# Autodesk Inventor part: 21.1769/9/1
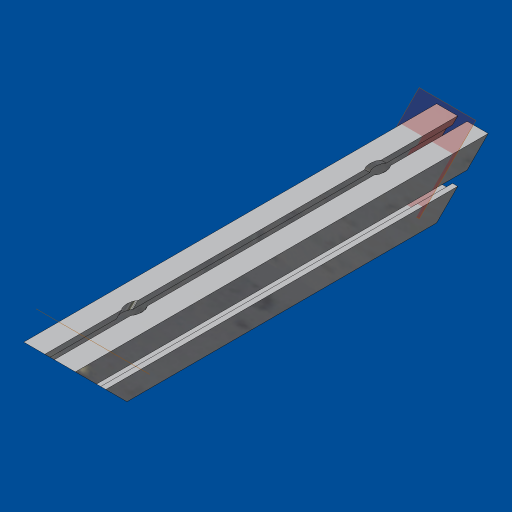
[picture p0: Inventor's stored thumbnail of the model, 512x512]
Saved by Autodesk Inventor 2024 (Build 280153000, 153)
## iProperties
Created: 2024-02
Part Number: 21.1769/9/1
Material: Aluminum-6061
Description: L = 14.17", MITER CUT & MILL TO 21.1761/9/1
Document SubType Name: Modeling
Designer: amoles
Stock Number: 20.1033 PROFILE 45X45 F
Density: 2.71 g/cm^3
Appearance: Aluminum - Dark
Vendor: F
FINISH: CLEAR ANODIZED
Author: amoles
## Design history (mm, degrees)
sketch "Sketch1"
  geometry: L1 (-4.1, -22.5)-(-4.1, -18) reference; L2 (-4.6, -18)-(-6.8, -18) reference; L3 (-6.8, -18)-(-6.8, -9.5) reference; L4 (-6.8, -9.5)-(-4.5, -7.2) reference; L5 (-4.5, -7.2)-(4.5, -7.2) reference; L6 (4.5, -7.2)-(6.8, -9.5) reference; L7 (6.8, -9.5)-(6.8, -18) reference; L8 (4.1, -18)-(4.1, -22.5) reference; L9 (22.5, -4.1)-(18, -4.1) reference; L10 (18, -4.6)-(18, -6.8) reference; L11 (18, -6.8)-(9.5, -6.8) reference; L12 (9.5, -6.8)-(7.2, -4.5) reference; L13 (7.2, -4.5)-(7.2, 4.5) reference; L14 (7.2, 4.5)-(9.5, 6.8) reference; L15 (9.5, 6.8)-(18, 6.8) reference; L16 (18, 4.1)-(22.5, 4.1) reference; L17 (22.5, 22.5)-(22.5, 4.4) reference; L18 (4.1, 22.5)-(4.1, 18) reference; L19 (4.6, 18)-(6.8, 18) reference; L20 (6.8, 18)-(6.8, 9.5) reference; L21 (6.8, 9.5)-(4.5, 7.2) reference; L22 (4.5, 7.2)-(-4.5, 7.2) reference; L23 (-4.5, 7.2)-(-6.8, 9.5) reference; L24 (-6.8, 9.5)-(-6.8, 18) reference; L25 (-4.1, 18)-(-4.1, 22.5) reference; L26 (-22.5, 22.5)-(-4.4, 22.5) reference; L27 (-22.5, 4.1)-(-18, 4.1) reference; L28 (-18, 6.8)-(-9.5, 6.8) reference; L29 (-9.5, 6.8)-(-7.2, 4.5) reference; L30 (-7.2, 4.5)-(-7.2, -4.5) reference; L31 (-7.2, -4.5)-(-9.5, -6.8) reference; L32 (-9.5, -6.8)-(-18, -6.8) reference; L33 (-18, -6.8)-(-18, -4.6) reference; L34 (-18, -4.1)-(-22.5, -4.1) reference; L35 (-22.5, -22.5)-(-22.5, -4.4) reference; L36 (-4.4, -22.5)-(-22.5, -22.5) reference; L37 (-4.596, -3.182)-(-3.263, -1.849) reference; L38 (-3.263, 1.849)-(-4.596, 3.182) reference; L39 (-4.596, 3.182)-(-3.182, 4.596) reference; L40 (-3.182, 4.596)-(-1.849, 3.263) reference; L41 (1.849, 3.263)-(3.182, 4.596) reference; L42 (3.182, 4.596)-(4.596, 3.182) reference; L43 (4.596, 3.182)-(3.263, 1.849) reference; L44 (3.263, -1.849)-(4.596, -3.182) reference; L45 (4.596, -3.182)-(3.182, -4.596) reference; L46 (3.182, -4.596)-(1.849, -3.263) reference; L47 (-1.849, -3.263)-(-3.182, -4.596) reference; L48 (-3.182, -4.596)-(-4.596, -3.182) reference; L49 (13.8, -8.8)-(20.5, -8.8) reference; L50 (20.5, -8.8)-(20.5, -15.5) reference; L51 (15.5, -20.5)-(8.8, -20.5) reference; L52 (8.8, -20.5)-(8.8, -13.8) reference; L53 (8.8, 13.8)-(8.8, 20.5) reference; L54 (8.8, 20.5)-(15.5, 20.5) reference; L55 (20.5, 15.5)-(20.5, 8.8) reference; L56 (20.5, 8.8)-(13.8, 8.8) reference; L57 (-13.8, 8.8)-(-20.5, 8.8) reference; L58 (-20.5, 8.8)-(-20.5, 15.5) reference; L59 (-15.5, 20.5)-(-8.8, 20.5) reference; L60 (-8.8, 20.5)-(-8.8, 13.8) reference; L61 (-8.8, -13.8)-(-8.8, -20.5) reference; L62 (-8.8, -20.5)-(-15.5, -20.5) reference; L63 (-20.5, -15.5)-(-20.5, -8.8) reference; L64 (-20.5, -8.8)-(-13.8, -8.8) reference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; A1 r 3.75 centre (0, 0) between (3.362, -1.66) and (3.362, 1.66) reference; A2 r 5 centre (13.8, -13.8) between (13.8, -8.8) and (8.8, -13.8) reference; A3 r 5 centre (15.5, -15.5) between (15.5, -20.5) and (20.5, -15.5) reference; A4 r 5 centre (13.8, 13.8) between (8.8, 13.8) and (13.8, 8.8) reference; A5 r 5 centre (15.5, 15.5) between (20.5, 15.5) and (15.5, 20.5) reference; A6 r 5 centre (-13.8, 13.8) between (-13.8, 8.8) and (-8.8, 13.8) reference; A7 r 5 centre (-15.5, 15.5) between (-15.5, 20.5) and (-20.5, 15.5) reference; A8 r 5 centre (-13.8, -13.8) between (-8.8, -13.8) and (-13.8, -8.8) reference; A9 r 5 centre (-15.5, -15.5) between (-20.5, -15.5) and (-15.5, -20.5) reference; A10 r 3.75 centre (0, 0) between (3.362, 1.66) and (3.263, 1.849) reference; A11 r 3.75 centre (0, 0) between (1.849, 3.263) and (-1.66, 3.362) reference; A12 r 3.75 centre (0, 0) between (-1.66, 3.362) and (-1.849, 3.263) reference; A13 r 3.75 centre (0, 0) between (-3.263, 1.849) and (-3.263, -1.849) reference; A14 r 3.75 centre (0, 0) between (-1.849, -3.263) and (-1.66, -3.362) reference; A15 r 3.75 centre (0, 0) between (-1.66, -3.362) and (1.849, -3.263) reference; A16 r 3.75 centre (0, 0) between (3.263, -1.849) and (3.362, -1.66) reference
  constraints: 160 end point, 32 point on circle, 30 horizontal, 30 vertical, 16 centre point, 144 other
extrude "Extrusion2" new body sketch "Sketch1" stored distance "d2" = 360; taper "d3" = 0 deg
sketch "Sketch2"
  geometry: L1 (0, 0)-(0, 18.4) reference; L2 (360, -26.6)-(0, -26.6) reference; L3 (0, 18.4)-(45, -26.6); L4 (0, -26.6)-(0, -8.2) reference; L5 (45, -26.6)-(0, -26.6); L6 (0, -26.6)-(0, 18.4); 3 further points
  constraints: 6 end point, 1 collinear, 1 point on line
  dimensions: "d4" = 45 deg angle of L4 L3
extrude "Extrusion3" cut sketch "Sketch2" distance "d5" = 50.8; taper "d6" = 0 deg
workplane "Work Plane1"
sketch "Sketch3"
  geometry: L1 (45, 0)-(26.6, 0) reference; L2 (45, 0)-(45, -26.022) reference; C1 r 6.5 at (22.5, -52.324); 1 further point
  constraints: 1 centre point
  dimensions: "d8" = 13 diameter of C1; "d9" = 52.324 distance from line of C1.centre L1; "d10" = 22.5 distance from line of C1.centre L2
extrude "Extrusion4" cut sketch "Sketch3" distance "d11" = 50.8; taper "d12" = 0 deg
sketch "Sketch4"
  geometry: L1 (-24.349, -48.796)-(-25.682, -46.91) reference; L2 (-19.318, -46.91)-(-20.651, -48.796) reference; C1 r 4.25 at (-22.5, -52.324); A1 r 6.5 centre (-22.5, -52.324) between (-18.329, -57.309) and (-26.671, -57.309) reference; 4 further points; 1 other entity
  constraints: 1 centre point, 1 concentric, 1 other
  dimensions: "d13" = 8.5 diameter of C1
extrude "Extrusion5" cut sketch "Sketch4" distance "d14" = 50.8; taper "d15" = 0 deg
mirror "Mirror1"
body "Solid2"
workplane "Work Plane2"
other parameters: "d7" = -21.59
